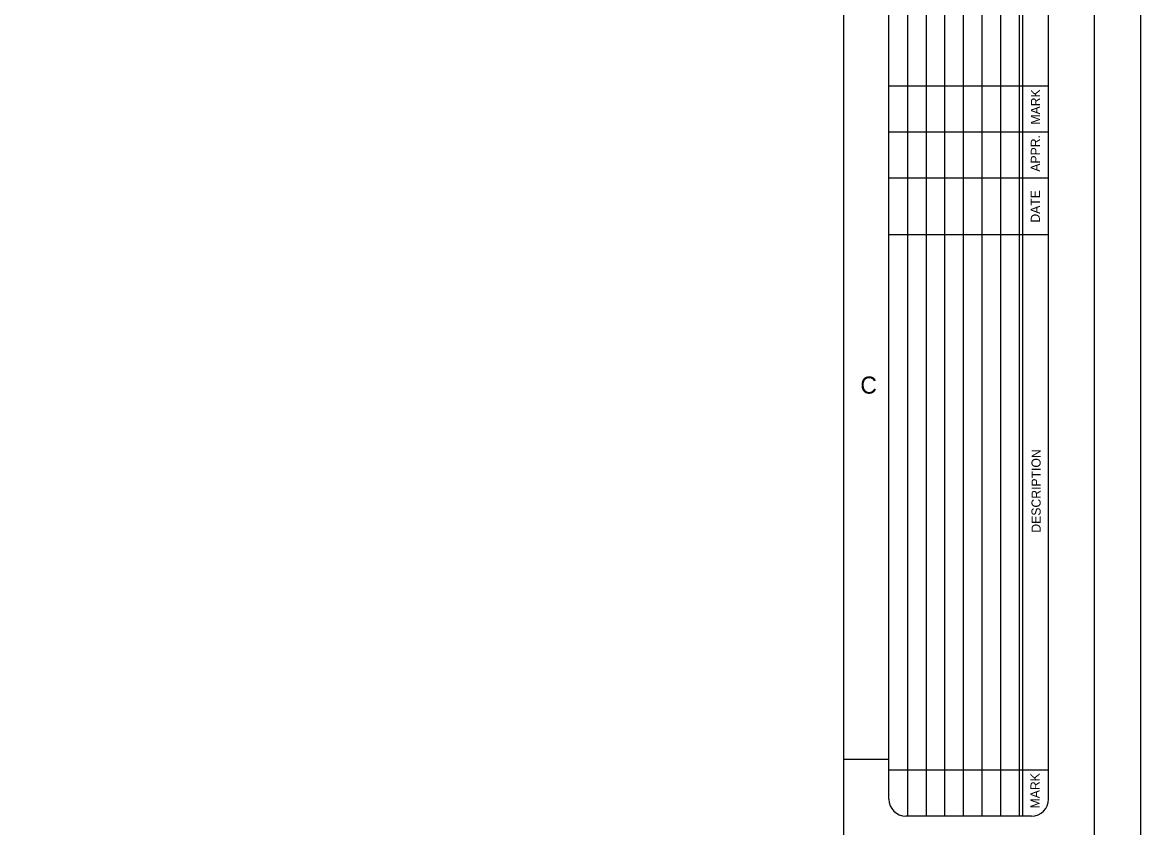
# Model space of a CAD drawing. Extents: x 22369.6 to 22428.3, y 22369.6 to 22415.
# Drawn here: x 22411.94 to 22428.29, y 22391.29 to 22403.06 of the extents above; entities that cross this region are included whole.
import ezdxf

# ---------------------------------------------------------------- set-up
doc = ezdxf.new("R2010")
doc.units = 0
for name, color, linetype in [('Level 1', 7, 'Continuous'), ('Level 10', 7, 'Continuous'), ('Level 7', 7, 'Continuous'), ('Level 9', 7, 'Continuous')]:
    doc.layers.add(name, color=color, linetype=linetype)

msp = doc.modelspace()

# ---------------------------------------------------------------- linework, layer by layer
at = {"layer": 'Level 1'}
for p, q in [((22424.88, 22411.456), (22424.88, 22391.456)), ((22425.152, 22411.456), (22425.152, 22391.456)), ((22425.424, 22411.456), (22425.424, 22391.456)), ((22425.696, 22411.456), (22425.696, 22391.456)), ((22425.968, 22411.456), (22425.968, 22391.456)), ((22426.24, 22411.456), (22426.24, 22391.456)), ((22426.512, 22411.456), (22426.512, 22391.456)), ((22426.56, 22411.456), (22426.56, 22391.456)), ((22426.944, 22401.456), (22424.608, 22401.456)), ((22426.694, 22391.456), (22424.858, 22391.456))]:
    msp.add_line(p, q, dxfattribs=at)
msp.add_lwpolyline([(22369.621, 22414.955), (22428.288, 22414.955), (22428.288, 22369.621), (22369.621, 22369.621)], close=True, dxfattribs=at)
for points in [[(22424.608, 22391.706), (22424.608, 22411.206)], [(22426.944, 22391.706), (22426.944, 22411.206)]]:
    msp.add_lwpolyline(points, dxfattribs=at)
for centre, start, end in [((22424.858, 22391.706), 180, 270), ((22426.694, 22391.706), 270, 0)]:
    msp.add_arc(centre, 0.25, start, end, dxfattribs=at)
at = {"layer": 'Level 10'}
msp.add_line((22423.952, 22392.288), (22424.608, 22392.288), dxfattribs=at)
at = {"layer": 'Level 7'}
for p, q in [((22426.944, 22400.784), (22424.608, 22400.784)), ((22426.944, 22399.951), (22424.608, 22399.951)), ((22426.944, 22392.128), (22424.608, 22392.128))]:
    msp.add_line(p, q, dxfattribs=at)
msp.add_lwpolyline([(22426.944, 22402.128), (22424.608, 22402.128)], dxfattribs=at)
at = {"layer": 'Level 9'}
msp.add_line((22427.616, 22370.288), (22427.616, 22414.288), dxfattribs=at)
msp.add_lwpolyline([(22423.952, 22370.288), (22423.952, 22414.288)], dxfattribs=at)

# ---------------------------------------------------------------- texts
at = {"layer": 'Level 1'}
for s, height, p in [('MARK', 0.1333, (22426.819, 22401.565)), ('APPR.', 0.1333, (22426.816, 22400.877)), ('DATE', 0.1333, (22426.816, 22400.132)), ('DESCRIPTION', 0.13333, (22426.827, 22395.6)), ('MARK', 0.1333, (22426.812, 22391.569))]:
    msp.add_text(s, height=height, rotation=90, dxfattribs=at).set_placement(p)
msp.add_text('C', height=0.25, dxfattribs=at).set_placement((22424.192, 22397.632))

doc.saveas('drawing.dxf')
